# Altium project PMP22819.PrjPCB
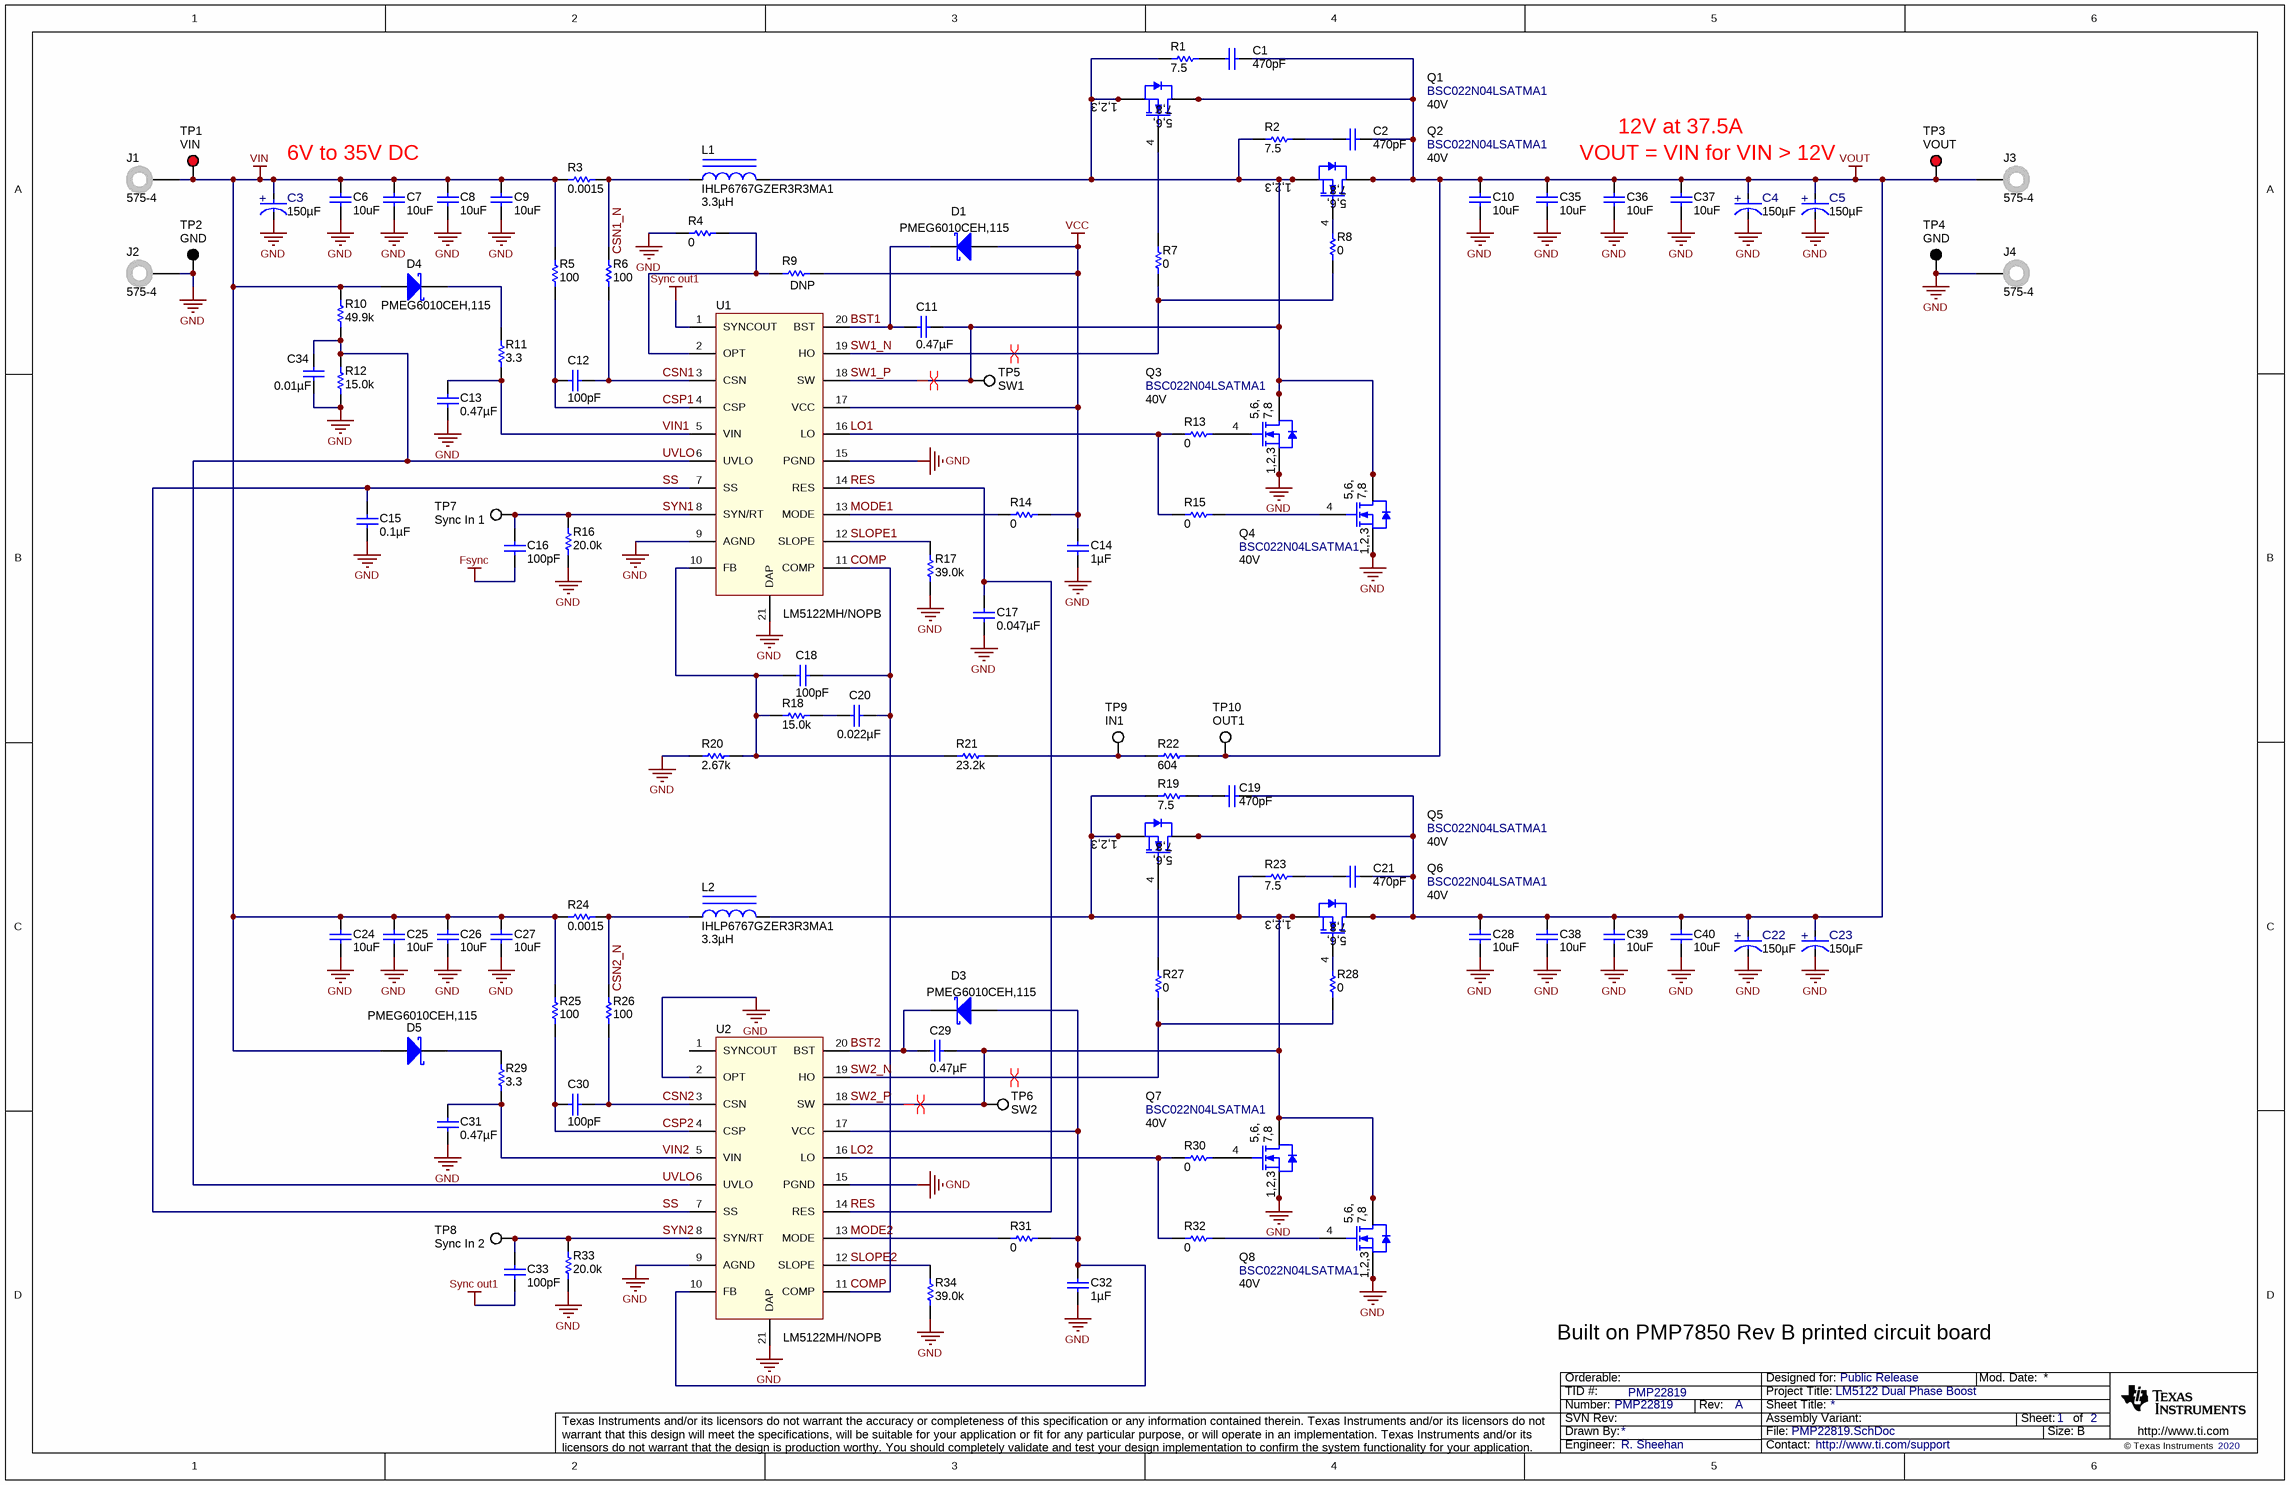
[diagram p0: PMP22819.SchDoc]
CopyrightYear: 2020; PCB_Layout: R. Sheehan; PCB_Rev: A; PRJ_Customer: Public Release; PRJ_Engineer: R. Sheehan; PRJ_Number: PMP22819; PRJ_Title: LM5122 Dual Phase Boost; SCH_Rev: A; TechSupport: http://www.ti.com/support; TID: PMP22819
2 sheets, 115 parts. Net scope: global (net labels, ports and power ports of the same name join across sheets).
Board file: PMP22819 PCB.PcbDoc
Sheets:
  PMP22819.SchDoc
  PMP22819 Hardware.SchDoc

## Sheet PMP22819.SchDoc
size 431 x 279 mm; DocumentNumber: 1; SheetNumber: 1; SheetTotal: 2; PageSetup: Record=PageOptions¦CenterHorizontal=True¦CenterVertical=True¦PrintScale=0.70¦XCorrection=1.00¦YCorrection=1.00¦PrintKind=1¦BorderSize=5000000¦LeftOffset=0¦BottomOffset=0¦Orientation=2¦PaperLength=1000¦PaperWidth=1000¦Scale=100¦PaperSource=15¦PrintQuality=600¦MediaType=1¦DitherType=10¦PaperKind=11x17¦PrintScaleMode=1

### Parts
C1  ValueDisplayed: 470pF  [0805_HV]  (hidden comment: GRM2165C2A471JA01D)
C2  ValueDisplayed: 470pF  [0805_HV]  (hidden comment: GRM2165C2A471JA01D)
C3  Cap_F: 150µF  [FP-EEH-ZS1J151V_RADIAL-MFG]  (hidden comment: EEH-ZS1J151V)
C4  Cap_F: 150µF  [FP-EEH-ZS1J151V_RADIAL-MFG]  (hidden comment: EEH-ZS1J151V)
C5  Cap_F: 150µF  [FP-EEH-ZS1J151V_RADIAL-MFG]  (hidden comment: EEH-ZS1J151V)
C6  ValueDisplayed: 10uF  [1210_280]  (hidden comment: C3225X7R1E106M250AC)
C7  ValueDisplayed: 10uF  [1210_280]  (hidden comment: C3225X7R1E106M250AC)
C8  ValueDisplayed: 10uF  [1210_280]  (hidden comment: C3225X7R1E106M250AC)
C9  ValueDisplayed: 10uF  [1210_280]  (hidden comment: C3225X7R1E106M250AC)
C10  ValueDisplayed: 10uF  [1210_280]  (hidden comment: C3225X7R1E106M250AC)
C11  ValueDisplayed: 0.47µF  [0603_HV]  (hidden comment: GRM188R71E474KA12D)
C12  ValueDisplayed: 100pF  [0603_HV]  (hidden comment: GRM1885C1H101JA01D)
C13  ValueDisplayed: 0.47µF  [0603_HV]  (hidden comment: GRM188R71E474KA12D)
C14  ValueDisplayed: 1µF  [0603_HV]  (hidden comment: GRM188R71E105KA12D)
C15  ValueDisplayed: 0.1µF  [0603_HV]  (hidden comment: GRM188R71E104KA01D)
C16  ValueDisplayed: 100pF  [0603_HV]  (hidden comment: GRM1885C1H101JA01D)
C17  ValueDisplayed: 0.047µF  [0603_HV]  (hidden comment: GRM188R71E473KA01D)
C18  ValueDisplayed: 100pF  [0603_HV]  (hidden comment: GRM1885C1H101JA01D)
C19  ValueDisplayed: 470pF  [0805_HV]  (hidden comment: GRM2165C2A471JA01D)
C20  ValueDisplayed: 0.022µF  [0603_HV]  (hidden comment: C0603C223K3RACTU)
C21  ValueDisplayed: 470pF  [0805_HV]  (hidden comment: GRM2165C2A471JA01D)
C22  Cap_F: 150µF  [FP-EEH-ZS1J151V_RADIAL-MFG]  (hidden comment: EEH-ZS1J151V)
C23  Cap_F: 150µF  [FP-EEH-ZS1J151V_RADIAL-MFG]  (hidden comment: EEH-ZS1J151V)
C24  ValueDisplayed: 10uF  [1210_280]  (hidden comment: C3225X7R1E106M250AC)
C25  ValueDisplayed: 10uF  [1210_280]  (hidden comment: C3225X7R1E106M250AC)
C26  ValueDisplayed: 10uF  [1210_280]  (hidden comment: C3225X7R1E106M250AC)
C27  ValueDisplayed: 10uF  [1210_280]  (hidden comment: C3225X7R1E106M250AC)
C28  ValueDisplayed: 10uF  [1210_280]  (hidden comment: C3225X7R1E106M250AC)
C29  ValueDisplayed: 0.47µF  [0603_HV]  (hidden comment: GRM188R71E474KA12D)
C30  ValueDisplayed: 100pF  [0603_HV]  (hidden comment: GRM1885C1H101JA01D)
C31  ValueDisplayed: 0.47µF  [0603_HV]  (hidden comment: GRM188R71E474KA12D)
C32  ValueDisplayed: 1µF  [0603_HV]  (hidden comment: GRM188R71E105KA12D)
C33  ValueDisplayed: 100pF  [0603_HV]  (hidden comment: GRM1885C1H101JA01D)
C34  ValueDisplayed: 0.01µF  [0603_HV]  (hidden comment: GRM188R71C103KA01D)
C35  ValueDisplayed: 10uF  [1210_280]  (hidden comment: C3225X7R1E106M250AC)
C36  ValueDisplayed: 10uF  [1210_280]  (hidden comment: C3225X7R1E106M250AC)
C37  ValueDisplayed: 10uF  [1210_280]  (hidden comment: C3225X7R1E106M250AC)
C38  ValueDisplayed: 10uF  [1210_280]  (hidden comment: C3225X7R1E106M250AC)
C39  ValueDisplayed: 10uF  [1210_280]  (hidden comment: C3225X7R1E106M250AC)
C40  ValueDisplayed: 10uF  [1210_280]  (hidden comment: C3225X7R1E106M250AC)
D1  PMEG6010CEH,115  [SOD-123F]
D3  PMEG6010CEH,115  [SOD-123F]
D4  PMEG6010CEH,115  [SOD-123F]
D5  PMEG6010CEH,115  [SOD-123F]
J1  575-4  [Keystone_575-4]
J2  575-4  [Keystone_575-4]
J3  575-4  [Keystone_575-4]
J4  575-4  [Keystone_575-4]
L1  IHLP6767GZER3R3MA1  ValueDisplayed: 3.3µH  [IHLP6767GZ]
L2  IHLP6767GZER3R3MA1  ValueDisplayed: 3.3µH  [IHLP6767GZ]
Q1  BSC022N04LSATMA1  value 40V  [PG-TDSON-8]
Q2  BSC022N04LSATMA1  value 40V  [PG-TDSON-8]
Q3  BSC022N04LSATMA1  value 40V  [PG-TDSON-8]
Q4  BSC022N04LSATMA1  value 40V  [PG-TDSON-8]
Q5  BSC022N04LSATMA1  value 40V  [PG-TDSON-8]
Q6  BSC022N04LSATMA1  value 40V  [PG-TDSON-8]
Q7  BSC022N04LSATMA1  value 40V  [PG-TDSON-8]
Q8  BSC022N04LSATMA1  value 40V  [PG-TDSON-8]
R1  value 7.5  [2010M]  (hidden comment: ERJ-12ZYJ7R5U)
R2  value 7.5  [2010M]  (hidden comment: ERJ-12ZYJ7R5U)
R3  value 0.0015  [2512M]  (hidden comment: ERJ-M1WTF1M5U)
R4  value 0  [0603_HV]  (hidden comment: ERJ-3GEY0R00V)
R5  value 100  [0603_HV]  (hidden comment: CRCW0603100RFKEA)
R6  value 100  [0603_HV]  (hidden comment: CRCW0603100RFKEA)
R7  value 0  [0603_HV]  (hidden comment: ERJ-3GEY0R00V)
R8  value 0  [0603_HV]  (hidden comment: ERJ-3GEY0R00V)
R9  DNP  [0603_HV]
R10  value 49.9k  [0603_HV]  (hidden comment: CRCW060349K9FKEA)
R11  value 3.3  [0603_HV]  (hidden comment: CRCW06033R30JNEA)
R12  value 15.0k  [0603_HV]  (hidden comment: RC0603FR-0715KL)
R13  value 0  [0603_HV]  (hidden comment: ERJ-3GEY0R00V)
R14  value 0  [0603_HV]  (hidden comment: ERJ-3GEY0R00V)
R15  value 0  [0603_HV]  (hidden comment: ERJ-3GEY0R00V)
R16  value 20.0k  [0603_HV]  (hidden comment: CRCW060320K0FKEA)
R17  value 39.0k  [0603_HV]  (hidden comment: RC0603FR-0739KL)
R18  value 15.0k  [0603_HV]  (hidden comment: CRCW060315K0FKEA)
R19  value 7.5  [2010M]  (hidden comment: ERJ-12ZYJ7R5U)
R20  value 2.67k  [0603_HV]  (hidden comment: CRCW06032K67FKEA)
R21  value 23.2k  [0603]  (hidden comment: CRCW060323K2FKEA)
R22  value 604  [0805_HV]  (hidden comment: CRCW0805604RFKEA)
R23  value 7.5  [2010M]  (hidden comment: ERJ-12ZYJ7R5U)
R24  value 0.0015  [2512M]  (hidden comment: ERJ-M1WTF1M5U)
R25  value 100  [0603_HV]  (hidden comment: CRCW0603100RFKEA)
R26  value 100  [0603_HV]  (hidden comment: CRCW0603100RFKEA)
R27  value 0  [0603_HV]  (hidden comment: ERJ-3GEY0R00V)
R28  value 0  [0603_HV]  (hidden comment: ERJ-3GEY0R00V)
R29  value 3.3  [0603_HV]  (hidden comment: CRCW06033R30JNEA)
R30  value 0  [0603_HV]  (hidden comment: ERJ-3GEY0R00V)
R31  value 0  [0603_HV]  (hidden comment: ERJ-3GEY0R00V)
R32  value 0  [0603_HV]  (hidden comment: ERJ-3GEY0R00V)
R33  value 20.0k  [0603]  (hidden comment: CRCW060320K0FKEA)
R34  value 39.0k  [0603_HV]  (hidden comment: RC0603FR-0739KL)
TP1  VIN  [Keystone5000]
TP2  GND  [Keystone5001]
TP3  VOUT  [Keystone5000]
TP4  GND  [Keystone5001]
TP5  SW1  [Keystone5002]
TP6  SW2  [Keystone5002]
TP7  Sync In 1  [Keystone5002]
TP8  Sync In 2  [Keystone5002]
TP9  IN1  [Keystone5002]
TP10  OUT1  [Keystone5002]
U1  LM5122MH/NOPB  [MXA20A_L - 10milVia]
U2  LM5122MH/NOPB  [MXA20A_L - 10milVia]

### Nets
Fsync: C16.1
GND: C3.1(CATHODE) C4.1(CATHODE) C5.1(CATHODE) C6.2 C7.2 C8.2 C9.2 C10.2 C13.2 C14.2 C15.2 C17.2 C22.1(CATHODE) C23.1(CATHODE) C24.2 C25.2 C26.2 C27.2 C28.2 C31.2 C32.2 C34.2 C35.2 C36.2 C37.2 C38.2 C39.2 C40.2 J2.1 J4.1 Q3.1(S) Q3.2(S) Q3.3(S) Q4.1(S) Q4.2(S) Q4.3(S) Q7.1(S) Q7.2(S) Q7.3(S) Q8.1(S) Q8.2(S) Q8.3(S) R4.1 R12.1 R16.1 R17.1 R20.2 R33.1 R34.1 TP2.1 TP4.1 U1.9(AGND) U1.15(PGND) U1.21(DAP) U2.2(OPT) U2.9(AGND) U2.15(PGND) U2.21(DAP)
Sync out1: C33.1 U1.1(SYNCOUT)
VCC: C14.1 D1.2(A) R9.2 R14.2 U1.17(VCC)
VIN: C3.2(ANODE) C6.1 C7.1 C8.1 C9.1 C24.1 C25.1 C26.1 C27.1 D4.2(A) D5.2(A) J1.1 R3.1 R5.2 R10.2 R24.1 R25.2 TP1.1
VOUT: C1.1 C2.1 C4.2(ANODE) C5.2(ANODE) C10.1 C19.1 C21.1 C22.2(ANODE) C23.2(ANODE) C28.1 C35.1 C36.1 C37.1 C38.1 C39.1 C40.1 J3.1 Q1.5(D) Q1.6(D) Q1.7(D) Q1.8(D) Q1.9(D) Q2.5(D) Q2.6(D) Q2.7(D) Q2.8(D) Q2.9(D) Q5.5(D) Q5.6(D) Q5.7(D) Q5.8(D) Q5.9(D) Q6.5(D) Q6.6(D) Q6.7(D) Q6.8(D) Q6.9(D) R22.1 TP3.1 TP10.1
BST1: C11.2 D1.1(K) U1.20(BST)
BST2: C29.2 D3.1(K) U2.20(BST)
COMP: C18.2 C20.2 U1.11(COMP) U2.11(COMP)
CSN1: C12.1 R6.1 U1.3(CSN)
CSN1_N: L1.1 R3.2 R6.2
CSN2: C30.1 R26.1 U2.3(CSN)
CSN2_N: L2.1 R24.2 R26.2
CSP1: C12.2 R5.1 U1.4(CSP)
CSP2: C30.2 R25.1 U2.4(CSP)
LO1: R13.2 R15.2 U1.16(LO)
LO2: R30.2 R32.2 U2.16(LO)
MODE1: R14.1 U1.13(MODE)
MODE2: R31.1 U2.13(MODE)
RES: C17.1 U1.14(RES) U2.14(RES)
SLOPE1: R17.2 U1.12(SLOPE)
SLOPE2: R34.2 U2.12(SLOPE)
SS: C15.1 U1.7(SS) U2.7(SS)
SW1_N: R7.2 R8.2 U1.19(HO)
SW1_P: C11.1 L1.2 Q1.1(S) Q1.2(S) Q1.3(S) Q2.1(S) Q2.2(S) Q2.3(S) Q3.5(D) Q3.6(D) Q3.7(D) Q3.8(D) Q3.9(D) Q4.5(D) Q4.6(D) Q4.7(D) Q4.8(D) Q4.9(D) R1.2 R2.2 TP5.1 U1.18(SW)
SW2_N: R27.2 R28.2 U2.19(HO)
SW2_P: C29.1 L2.2 Q5.1(S) Q5.2(S) Q5.3(S) Q6.1(S) Q6.2(S) Q6.3(S) Q7.5(D) Q7.6(D) Q7.7(D) Q7.8(D) Q7.9(D) Q8.5(D) Q8.6(D) Q8.7(D) Q8.8(D) Q8.9(D) R19.2 R23.2 TP6.1 U2.18(SW)
SYN1: C16.2 R16.2 TP7.1 U1.8(SYN/RT)
SYN2: C33.2 R33.2 TP8.1 U2.8(SYN/RT)
UVLO: C34.1 R10.1 R12.2 U1.6(UVLO) U2.6(UVLO)
VIN1: C13.1 R11.1 U1.5(VIN)
VIN2: C31.1 R29.1 U2.5(VIN)
NetC1_2: C1.2 R1.1
NetC2_2: C2.2 R2.1
NetC18_1: C18.1 R18.1 R20.1 R21.1 U1.10(FB)
NetC19_2: C19.2 R19.1
NetC20_1: C20.1 R18.2
NetC21_2: C21.2 R23.1
NetC32_1: C32.1 D3.2(A) R31.2 U2.10(FB) U2.17(VCC)
NetD4_1: D4.1(K) R11.2
NetD5_1: D5.1(K) R29.2
NetQ1_4: Q1.4(G) R7.1
NetQ2_4: Q2.4(G) R8.1
NetQ3_4: Q3.4(G) R13.1
NetQ4_4: Q4.4(G) R15.1
NetQ5_4: Q5.4(G) R27.1
NetQ6_4: Q6.4(G) R28.1
NetQ7_4: Q7.4(G) R30.1
NetQ8_4: Q8.4(G) R32.1
NetR4_2: R4.2 R9.1 U1.2(OPT)
NetR21_2: R21.2 R22.2 TP9.1

Not connected (* = marked no-connect by the designer): U2 1(SYNCOUT)

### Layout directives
differential pair: SW1_N, SW1_P, SW2_N, SW2_P

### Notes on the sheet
- 6V to 35V DC
- 12V at 37.5A
- VOUT = VIN for VIN > 12V
- Built on PMP7850 Rev B printed circuit board

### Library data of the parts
C1 C2 C19 C21 = GRM2165C2A471JA01D: CAP, CERM, 470pF, 100V, +/-5%, C0G/NP0, 0805; Manufacturer: MuRata; Polarized: N; CompType: Capacitor; U/M: EA; Cap_F: 0.00000000047; Tolerance_%: 5; VDC_V: 100; TaMin_C: -55; TaMax_C: 125; Cap_Case: 0805
C3-C5 C22 C23 = CMP-0087122-1: HYBRID CAPACITOR, SMD 63V150UF 1; Manufacturer: Panasonic; Tolerance_%: 20%; VDC_V: 63V; IRMS_A: 3.5A; AEC Grade: Grade 1; AEC Qualified: Yes; SizeZ_mm: 16.8mm; Symbol Name: SYM-EEH-ZS1J151V
C6 = CMP-0009117-1: CAP, CERM, 10 uF, 25 V, +/- 20%, X7R, 1210; Manufacturer: TDK; Polarized: N; Value: 10uF; U/M: EA; Cap_F: 10µF; Value1: Unknown; VDC_V: 25V; TaMin_C: -55°C; TaMax_C: 125°C; Cap_Case: 1210; SizeAreaWB_mm2: 14.7; SizeZ_mm: 2.8; SizeX_mm: 3.2; SizeY_mm: 2.5; SizeArea_mm2: 8; AEC Category: Q200
C7-C10 C24-C28 C35-C40 = CMP-0009117-1: CAP, CERM, 10 uF, 25 V, +/- 20%, X7R, 1210; Manufacturer: TDK; Polarized: N; Value: 10uF; U/M: EA; Cap_F: 10µF; Value1: Unknown; VDC_V: 25V; TaMin_C: -55°C; TaMax_C: 125°C; Cap_Case: 1210; AEC Category: Q200; SizeArea_mm2: 8; SizeAreaWB_mm2: 14.7; SizeX_mm: 3.2; SizeY_mm: 2.5; SizeZ_mm: 2.8
C11 C13 C29 C31 = GRM188R71E474KA12D: CAP, CERM, 0.47uF, 25V, +/-10%, X7R, 0603; Manufacturer: MuRata; Polarized: N; CompType: Capacitor; U/M: EA; Cap_F: 0.00000047; Tolerance_%: 10; VDC_V: 25; TaMin_C: -55; TaMax_C: 125; Cap_Case: 0603
C12 C16 C18 C30 C33 = GRM1885C1H101JA01D: CAP, CERM, 100pF, 50V, +/-5%, C0G/NP0, 0603; Manufacturer: MuRata; Polarized: N; CompType: Capacitor; U/M: EA; Cap_F: 0.0000000001; Tolerance_%: 5; VDC_V: 50; TaMin_C: -55; TaMax_C: 125; Cap_Case: 0603
C14 C32 = GRM188R71E105KA12D: CAP, CERM, 1uF, 25V, +/-10%, X7R, 0603; Manufacturer: MuRata; Polarized: N; CompType: Capacitor; U/M: EA; Cap_F: 0.000001; Tolerance_%: 10; VDC_V: 25; TaMin_C: -55; TaMax_C: 125; Cap_Case: 0603
C15 = GRM188R71E104KA01D: CAP, CERM, 0.1uF, 25V, +/-10%, X7R, 0603; Manufacturer: MuRata; Polarized: N; CompType: Capacitor; U/M: EA; Cap_F: 0.0000001; Tolerance_%: 10; VDC_V: 25; TaMin_C: -55; TaMax_C: 125; Cap_Case: 0603
C17 = GRM188R71E473KA01D: CAP, CERM, 0.047uF, 25V, +/-10%, X7R, 0603; Manufacturer: MuRata; Polarized: N; CompType: Capacitor; U/M: EA; Cap_F: 0.000000047; Tolerance_%: 10; VDC_V: 25; TaMin_C: -55; TaMax_C: 125; Cap_Case: 0603
C20 = C0603C223K3RACTU: CAP, CERM, 0.022uF, 25V, +/-10%, X7R, 0603; Manufacturer: Kemet; Polarized: N; CompType: Capacitor; U/M: EA; Cap_F: 0.000000022; Tolerance_%: 10; VDC_V: 25; TaMin_C: -55; TaMax_C: 125; Cap_Case: 0603
C34 = GRM188R71C103KA01D: CAP, CERM, 0.01uF, 16V, +/-10%, X7R, 0603; Manufacturer: MuRata; Polarized: N; CompType: Capacitor; U/M: EA; Cap_F: 0.00000001; Tolerance_%: 10; VDC_V: 16; TaMin_C: -55; TaMax_C: 125; Cap_Case: 0603
D1 D3-D5 = PMEG6010CEH,115: Diode, Schottky, 60V, 1A, SOD-123F; Manufacturer: NXP Semiconductor; U/M: EA; Vf_V: 0.57; Io_A: 1; Vr_V: 60; TJmax_C: 150; Value: 0.57V
J1-J4 = 575-4: Standard Banana Jack, Uninsulated, 5.5mm; Manufacturer: Keystone; Alternate Manufacturer: Any; Alternate PartNumber: Equivalent; CompType: Connector; U/M: EA
L1 L2 = IHLP6767GZER3R3MA1: INDUCTOR POWER 3.3UH 54A SMD; Manufacturer: Vishay-Dale; Alternate Manufacturer: Any; Alternate PartNumber: Equivalent; Ind_H: 1.0E-6; Imax_A: 41; Irms: 32A @ 40C rise; Isat: 49A @ 20% inductance drop; Value1: 0.0018 ohm; Material: Powdered Iron; Expr1028: Digi-Key; U/M: EA
Q1-Q8 = CMP-0078932-1: MOSFET, N-CH, 40 V, 100 A, PG-TDSON-8; Manufacturer: Infineon Technologies; Alternate Manufacturer: None; U/M: EA; ChType: N; Value1: 0.0032 ohm; Rdson45_ohm: 3.2m; Value2: 37 nC; QgTyp_nC: 37; Vgs_V: 20V; IdsMax_A: 100A; AEC Category: Q101; SizeArea_mm2: 29.351; SizeAreaWB_mm2: 55.131; SizeX_mm: 5.99; SizeY_mm: 4.9; SizeZ_mm: 1.12
R1 R2 R19 R23 = ERJ-12ZYJ7R5U: RESISTOR 7.5 OHM 3/4W 5% 2010; Manufacturer: Panasonic; Value_Code: 7R50; Tolerance_%: 5; Power_W: 1; Value2: 1W; VDC_V: 3; TempCo: -100 /+600 ppm/C; EIA_Code: E24; U/M: EA
R3 R24 = ERJ-M1WTF1M5U: RES, 0.0015 ohm, 1%, 1W, 2512; Manufacturer: Panasonic; CompType: Resistor; Value_Code: R0015; Tolerance_%: 1; TempCo: ppm/C; U/M: EA
R4 R7 R8 R13-R15 R27 R28 R30-R32 = ERJ-3GEY0R00V: RES, 0 ohm, 5%, 0.1W, 0603; Manufacturer: Panasonic; CompType: Resistor; Value_Code: 0000; Tolerance_%: 5; Power_W: 0.1; VDC_V: 50; TempCo: 600 ppm/C; EIA_Code: E24; U/M: EA
R5 R6 R25 R26 = CRCW0603100RFKEA: RES, 100 ohm, 1%, 0.1W, 0603; Manufacturer: Vishay-Dale; CompType: Resistor; Value_Code: 100R; Tolerance_%: 1; Power_W: 0.1; VDC_V: 75; TempCo: 100 ppm/C; EIA_Code: E96; U/M: EA
R9 = CRCW0603158KFKEA: RES, 158k ohm, 1%, 0.1W, 0603; Manufacturer: Vishay-Dale; CompType: Resistor; Res_ohm: 158000; Tolerance_%: 1; Power_W: 0.1; VDC_V: 75; TempCo: 100 ppm/C; EIA_Code: E96; U/M: EA
R10 = CRCW060349K9FKEA: RES, 49.9k ohm, 1%, 0.1W, 0603; Manufacturer: Vishay-Dale; CompType: Resistor; Res_ohm: 49900; Value_Code: 49k9; Tolerance_%: 1; Power_W: 0.1; VDC_V: 75; TempCo: 100 ppm/C; EIA_Code: E96; U/M: EA
R11 R29 = CRCW06033R30JNEA: RES, 3.3 ohm, 5%, 0.1W, 0603; Manufacturer: Vishay-Dale; CompType: Resistor; Value_Code: 3R30; Tolerance_%: 5; Power_W: 0.1; VDC_V: 75; TempCo: 200 ppm/C; EIA_Code: E24; U/M: EA
R12 = RC0603FR-0715KL: RES, 15.0k ohm, 1%, 0.1W, 0603; Manufacturer: Yageo America; CompType: Resistor; Res_ohm: 15000; Value_Code: 15k0; Tolerance_%: 1; Power_W: 0.1; VDC_V: 150; TempCo: 200 ppm/C; EIA_Code: E96; U/M: EA
R16 R33 = CRCW060320K0FKEA: RES, 20.0k ohm, 1%, 0.1W, 0603; Manufacturer: Vishay-Dale; CompType: Resistor; Res_ohm: 20000; Value_Code: 20k0; Tolerance_%: 1; Power_W: 0.1; VDC_V: 75; TempCo: 100 ppm/C; EIA_Code: E96; U/M: EA
R17 R34 = RC0603FR-0739KL: RES, 39.0k ohm, 1%, 0.1W, 0603; Manufacturer: Yageo America; CompType: Resistor; Res_ohm: 39000; Value_Code: 39k0; Tolerance_%: 1; Power_W: 0.1; VDC_V: 150; TempCo: 200 ppm/C; U/M: EA
R18 = CRCW060315K0FKEA: RES, 15.0k ohm, 1%, 0.1W, 0603; Manufacturer: Vishay-Dale; CompType: Resistor; Res_ohm: 15000; Value_Code: 15k0; Tolerance_%: 1; Power_W: 0.1; VDC_V: 75; TempCo: 100 ppm/C; EIA_Code: E96; U/M: EA
R20 = CRCW06032K67FKEA: RES, 2.67k ohm, 1%, 0.1W, 0603; Manufacturer: Vishay-Dale; CompType: Resistor; Res_ohm: 2670; Value_Code: 2k67; Tolerance_%: 1; Power_W: 0.1; VDC_V: 75; TempCo: 100 ppm/C; EIA_Code: E96; U/M: EA
R21 = CRCW060323K2FKEA: RES, 23.2k ohm, 1%, 0.1W, 0603; Manufacturer: Vishay-Dale; CompType: Resistor; Res_ohm: 23200; Value_Code: 23k2; Tolerance_%: 1; Power_W: 0.1; VDC_V: 75; TempCo: 100 ppm/C; EIA_Code: E96; U/M: EA
R22 = CRCW0805604RFKEA: RES, 604 ohm, 1%, 0.125W, 0805; Manufacturer: Vishay-Dale; CompType: Resistor; Value_Code: 604R; Tolerance_%: 1; Power_W: 0.125; VDC_V: 150; TempCo: 100 ppm/C; EIA_Code: E96; U/M: EA
TP1 TP3 = 5000: Test Point, TH, Miniature, Red; Manufacturer: Keystone; CompType: Test Point Loop; U/M: EA
TP2 TP4 = 5001: Test Point, TH, Miniature, Black; Manufacturer: Keystone; CompType: Test Point Loop; U/M: EA
TP5-TP10 = 5002: Test Point, TH, Miniature, White; Manufacturer: Keystone; Alternate Manufacturer: Any; Alternate PartNumber: Equivalent; CompType: Test Point Loop; U/M: EA
U1 U2 = LM5122: Manufacturer: Texas Instruments; SymbolCreator: bkinsc; CompType: IC; U/M: EA

## Sheet PMP22819 Hardware.SchDoc
size 431 x 279 mm; Date: Not shown in title block; ApprovedBy: Not shown in title block; CheckedBy: Not shown in title block; Author: Not shown in title block; CompanyName: Not shown in title block; Engineer: Not shown in title block; Organization: Not shown in title block; Address1: Not shown in title block; Address2: Not shown in title block; Address3: Not shown in title block; Address4: Not shown in title block; DocumentNumber: 2; Revision: Use project parameter SCH_Rev; SheetNumber: 2; SheetTotal: 2; PageSetup: Record=PageOptions¦CenterHorizontal=True¦CenterVertical=True¦PrintScale=1.00¦XCorrection=1.00¦YCorrection=1.00¦PrintKind=0¦BorderSize=5000000¦LeftOffset=0¦BottomOffset=0¦Orientation=2¦PaperLength=1000¦PaperWidth=1000¦Scale=100¦PaperSource=15¦PrintQuality=600¦MediaType=1¦DitherType=10¦PaperKind=Letter¦PrintScaleMode=1
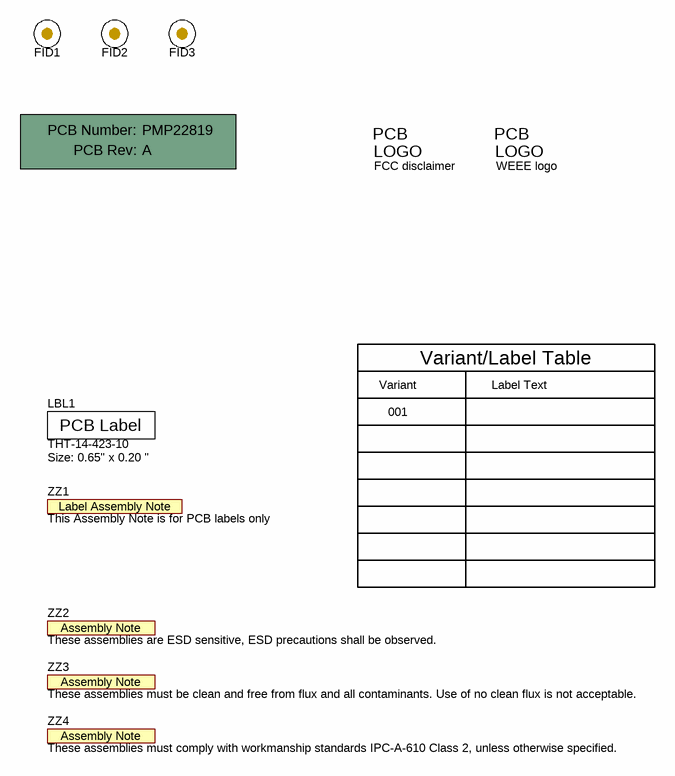
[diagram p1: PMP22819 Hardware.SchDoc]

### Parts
!PCB  Printed Circuit Board  (value not drawn)  (mechanical)
FID1  Fiducial  [Fiducial10-20]  (value not drawn)
FID2  Fiducial  [Fiducial10-20]  (value not drawn)
FID3  Fiducial  [Fiducial10-20]  (value not drawn)
LBL1  THT-14-423-10  Note: Size: 0.65" x 0.20 "  [Label_650x200]
Logo3  FCC disclaimer  [FCC_disclaimer]  (no BOM)
Logo4  WEEE logo  [WEEE_Minimum]  (no BOM)
ZZ1  This Assembly Note is for PCB labels only  [AssemblyNoteLabel]  (no BOM)
ZZ2  These assemblies are ESD sensitive, ESD precautions shall be observed.  [AssemblyNote]  (no BOM)
ZZ3  These assemblies must be clean and free from flux and all contaminants. Use of no clean flux is not acceptable.  [AssemblyNote]  (no BOM)
ZZ4  These assemblies must comply with workmanship standards IPC-A-610 Class 2, unless otherwise specified.  [AssemblyNote]  (no BOM)

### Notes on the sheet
- Variant
- Variant/Label Table
- Label Text
- 001

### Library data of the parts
!PCB = CMP-0003618-2: Manufacturer: Any; PartNumber: PMP22819
FID1-FID3 = CMP-0077181-1: Fiducial mark.  There is nothing to buy or mount.
LBL1 = CMP-0003625-1: Thermal Transfer Printable Labels, 0.650" W x 0.200" H - 10,000 per roll; Manufacturer: Brady; CompType: Label
Logo3 = CMP-0074847-1: FCC_disclaimer; Library Reference: Logo
Logo4 = CMP-0074769-1
ZZ1 = CMP-0003616-3
ZZ2 = CMP-0077236-1
ZZ3 = CMP-0077237-1
ZZ4 = CMP-0077238-1

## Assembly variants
001: not fitted FID1 FID2 FID3 R9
